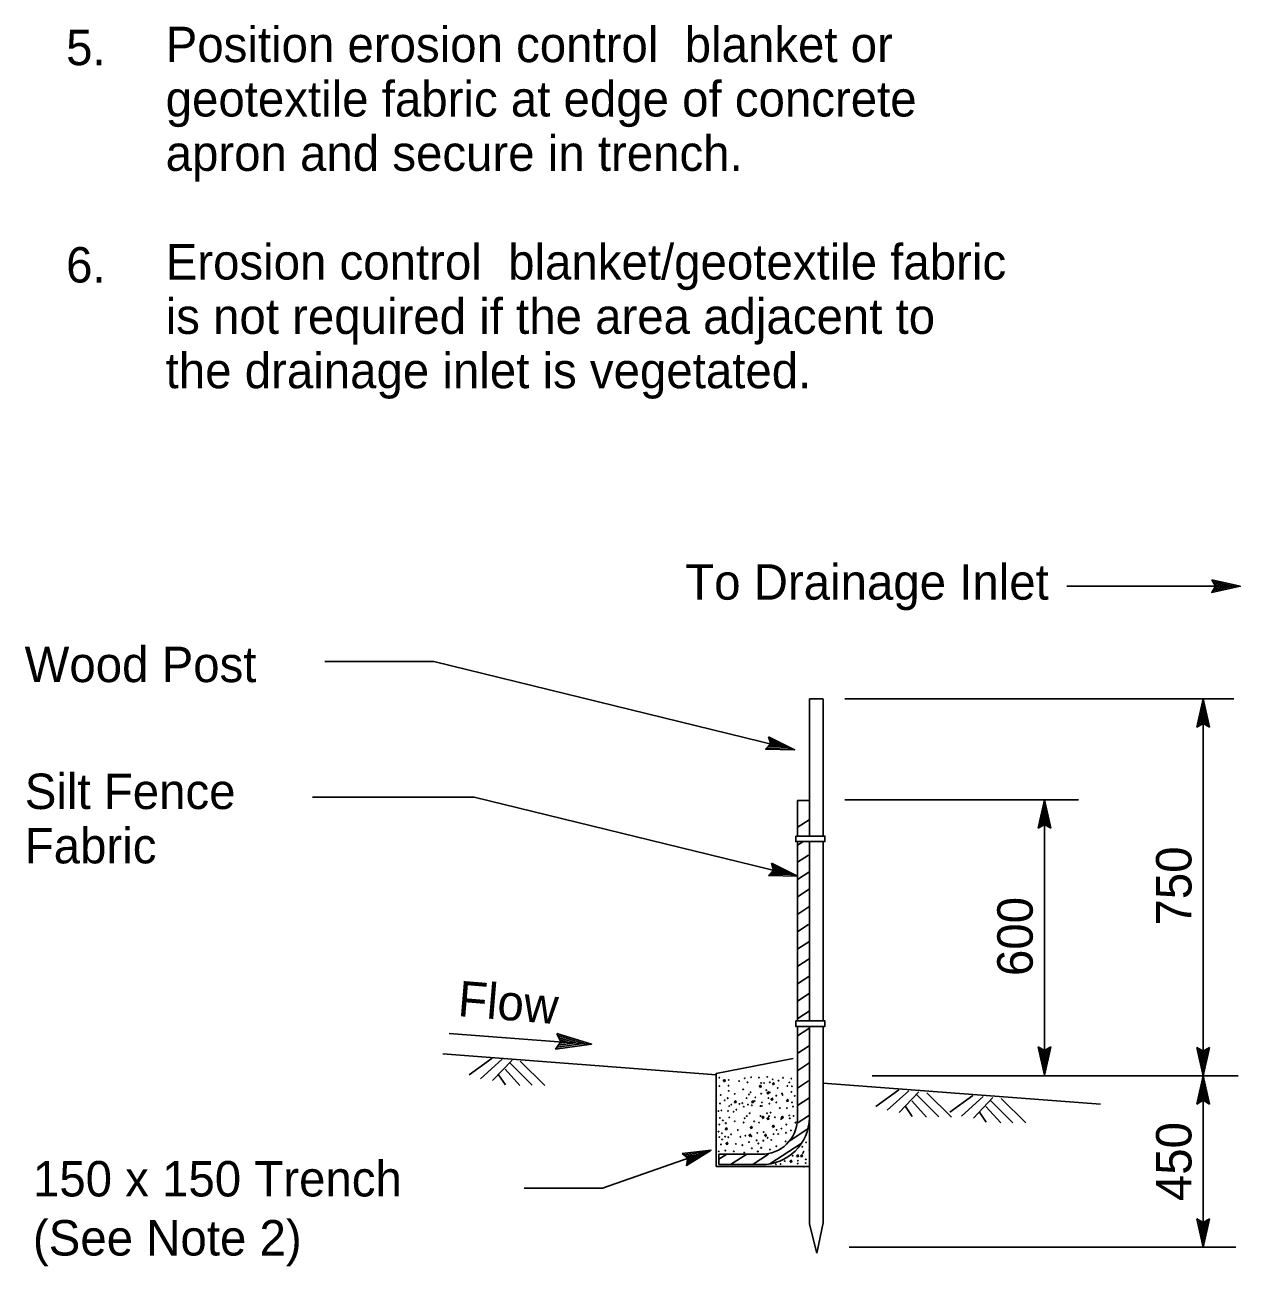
# Model space of a CAD drawing. Extents: x 6707406 to 6714471, y 1868570 to 1872341.
# Drawn here: x 6710120.7 to 6710367.6, y 1871743.9 to 1871996.1 of the extents above; entities that cross this region are included whole.
import ezdxf

# ---------------------------------------------------------------- set-up
doc = ezdxf.new("R2010")
doc.units = 0
for name, color, linetype in [('1 Control', 7, 'Continuous'), ('56 Stg 3 Anno', 7, 'Continuous'), ('57 Undefined', 7, 'Continuous'), ('59 Soundwall Ann', 7, 'Continuous'), ('60 Nongeo Data', 7, 'Continuous')]:
    doc.layers.add(name, color=color, linetype=linetype)

msp = doc.modelspace()

# ---------------------------------------------------------------- linework, layer by layer
at = {"layer": '1 Control'}
for p, q in [((6710361.8, 1871883.35), (6710361.8, 1871883.35)), ((6710361.8, 1871880.79), (6710361.8, 1871880.79)), ((6710367.56, 1871882.07), (6710367.56, 1871882.07)), ((6710271.77, 1871851.46), (6710271.77, 1871851.46)), ((6710271.16, 1871848.97), (6710271.16, 1871848.97)), ((6710277.06, 1871848.85), (6710277.06, 1871848.85)), ((6710228.77, 1871791.21), (6710228.77, 1871791.21)), ((6710235.82, 1871789.06), (6710235.82, 1871789.06)), ((6710228.52, 1871788.02), (6710228.52, 1871788.02))]:
    msp.add_line(p, q, dxfattribs=at)
for points in [[(6710361.8, 1871883.35), (6710367.56, 1871882.07), (6710361.8, 1871880.79), (6710362, 1871881.13), (6710366.22, 1871882.06), (6710362, 1871883.01), (6710362.21, 1871882.67), (6710364.91, 1871882.07), (6710362.21, 1871881.47), (6710362.41, 1871881.81), (6710363.58, 1871882.07), (6710362.41, 1871882.33), (6710362.57, 1871882.07), (6710361.8, 1871880.79), (6710362.57, 1871882.07)], [(6710271.77, 1871851.46), (6710277.06, 1871848.85), (6710271.16, 1871848.97), (6710271.44, 1871849.26), (6710275.76, 1871849.16), (6710271.89, 1871851.08), (6710272, 1871850.71), (6710274.48, 1871849.48), (6710271.72, 1871849.54), (6710272, 1871849.82), (6710273.2, 1871849.79), (6710272.12, 1871850.33), (6710272.21, 1871850.03), (6710271.16, 1871848.97), (6710272.21, 1871850.03)], [(6710228.77, 1871791.21), (6710235.82, 1871789.06), (6710228.52, 1871788.02), (6710228.81, 1871788.42), (6710234.16, 1871789.18), (6710228.99, 1871790.77), (6710229.21, 1871790.32), (6710232.52, 1871789.31), (6710229.1, 1871788.83), (6710229.39, 1871789.23), (6710230.87, 1871789.44), (6710229.43, 1871789.88), (6710229.6, 1871789.53), (6710228.52, 1871788.02), (6710229.6, 1871789.53)]]:
    msp.add_lwpolyline(points, close=True, dxfattribs=at)
at = {"layer": '56 Stg 3 Anno'}
for p, q in [((6710332.36, 1871882.07), (6710367.56, 1871882.07)), ((6710287.23, 1871859.19), (6710366.26, 1871859.19)), ((6710358.78, 1871853.43), (6710360.07, 1871859.19)), ((6710359.12, 1871853.63), (6710360.07, 1871857.86)), ((6710360.07, 1871782.62), (6710360.07, 1871859.19)), ((6710360.07, 1871859.19), (6710360.07, 1871859.19)), ((6710360.07, 1871859.19), (6710361.34, 1871853.43)), ((6710360.07, 1871857.85), (6710361, 1871853.65)), ((6710359.47, 1871853.86), (6710360.06, 1871856.53)), ((6710359.8, 1871854.03), (6710360.06, 1871855.21)), ((6710360.06, 1871856.53), (6710360.67, 1871853.82)), ((6710360.06, 1871855.21), (6710360.32, 1871854.05)), ((6710360.07, 1871854.19), (6710358.78, 1871853.43)), ((6710358.78, 1871853.43), (6710358.78, 1871853.43)), ((6710361.34, 1871853.43), (6710360.07, 1871854.19)), ((6710361.34, 1871853.43), (6710361.34, 1871853.43)), ((6710287.23, 1871838.66), (6710334.72, 1871838.66)), ((6710326.53, 1871832.9), (6710327.82, 1871838.66)), ((6710326.53, 1871832.9), (6710327.82, 1871838.66)), ((6710326.88, 1871833.11), (6710327.82, 1871837.33)), ((6710326.88, 1871833.11), (6710327.82, 1871837.33)), ((6710327.82, 1871782.74), (6710327.82, 1871838.66)), ((6710327.82, 1871838.66), (6710327.82, 1871838.66)), ((6710327.82, 1871838.66), (6710329.1, 1871832.9)), ((6710327.82, 1871838.66), (6710327.82, 1871838.66)), ((6710327.82, 1871838.66), (6710329.1, 1871832.9)), ((6710327.82, 1871837.32), (6710328.75, 1871833.12)), ((6710327.82, 1871837.32), (6710328.75, 1871833.12)), ((6710327.22, 1871833.33), (6710327.82, 1871836.01)), ((6710327.22, 1871833.33), (6710327.82, 1871836.01)), ((6710327.55, 1871833.5), (6710327.82, 1871834.68)), ((6710327.55, 1871833.5), (6710327.82, 1871834.68)), ((6710327.82, 1871836.01), (6710328.42, 1871833.3)), ((6710327.82, 1871836.01), (6710328.42, 1871833.3)), ((6710327.82, 1871834.68), (6710328.07, 1871833.52)), ((6710327.82, 1871834.68), (6710328.07, 1871833.52)), ((6710327.82, 1871833.67), (6710326.53, 1871832.9)), ((6710327.82, 1871833.67), (6710326.53, 1871832.9)), ((6710326.53, 1871832.9), (6710326.53, 1871832.9)), ((6710326.53, 1871832.9), (6710326.53, 1871832.9)), ((6710329.1, 1871832.9), (6710327.82, 1871833.67)), ((6710329.1, 1871832.9), (6710327.82, 1871833.67)), ((6710329.1, 1871832.9), (6710329.1, 1871832.9)), ((6710329.1, 1871832.9), (6710329.1, 1871832.9)), ((6710271.74, 1871823.29), (6710272.79, 1871824.35)), ((6710272.79, 1871824.35), (6710272.35, 1871825.78)), ((6710272.35, 1871825.78), (6710272.35, 1871825.78)), ((6710272.35, 1871825.78), (6710277.64, 1871823.16)), ((6710272.47, 1871825.4), (6710276.35, 1871823.48)), ((6710272.61, 1871825.01), (6710275.06, 1871823.79)), ((6710272.69, 1871824.65), (6710273.78, 1871824.11)), ((6710277.64, 1871823.16), (6710271.74, 1871823.29)), ((6710271.74, 1871823.29), (6710271.74, 1871823.29)), ((6710276.34, 1871823.48), (6710272.04, 1871823.57)), ((6710275.06, 1871823.79), (6710272.29, 1871823.85)), ((6710273.78, 1871824.11), (6710272.59, 1871824.14)), ((6710277.64, 1871823.16), (6710277.64, 1871823.16)), ((6710327.82, 1871782.74), (6710326.54, 1871788.5)), ((6710326.54, 1871788.5), (6710326.54, 1871788.5)), ((6710326.54, 1871788.5), (6710327.82, 1871787.73)), ((6710327.82, 1871784.07), (6710326.89, 1871788.27)), ((6710327.82, 1871785.39), (6710327.22, 1871788.1)), ((6710327.82, 1871786.71), (6710327.57, 1871787.88)), ((6710327.82, 1871787.73), (6710329.11, 1871788.5)), ((6710329.11, 1871788.5), (6710327.82, 1871782.74)), ((6710328.77, 1871788.29), (6710327.82, 1871784.06)), ((6710328.42, 1871788.06), (6710327.82, 1871785.39)), ((6710328.09, 1871787.89), (6710327.82, 1871786.71)), ((6710329.11, 1871788.5), (6710329.11, 1871788.5)), ((6710360.07, 1871782.62), (6710358.79, 1871788.38)), ((6710358.79, 1871788.38), (6710358.79, 1871788.38)), ((6710358.79, 1871788.38), (6710360.07, 1871787.61)), ((6710360.06, 1871783.95), (6710359.13, 1871788.15)), ((6710360.07, 1871785.27), (6710359.47, 1871787.98)), ((6710360.07, 1871786.6), (6710359.81, 1871787.76)), ((6710360.07, 1871787.61), (6710361.35, 1871788.38)), ((6710361.35, 1871788.38), (6710360.07, 1871782.62)), ((6710361.01, 1871788.17), (6710360.07, 1871783.94)), ((6710360.67, 1871787.95), (6710360.07, 1871785.27)), ((6710360.33, 1871787.78), (6710360.07, 1871786.6)), ((6710361.35, 1871788.38), (6710361.35, 1871788.38)), ((6710292.82, 1871782.62), (6710367.14, 1871782.62)), ((6710327.82, 1871782.74), (6710327.82, 1871782.74)), ((6710358.78, 1871776.86), (6710360.07, 1871782.62)), ((6710360.07, 1871747.79), (6710360.07, 1871782.62)), ((6710360.07, 1871782.62), (6710360.07, 1871782.62)), ((6710360.07, 1871782.62), (6710360.07, 1871782.62)), ((6710360.07, 1871782.62), (6710361.34, 1871776.86)), ((6710359.12, 1871777.07), (6710360.07, 1871781.29)), ((6710359.47, 1871777.29), (6710360.06, 1871779.97)), ((6710360.06, 1871779.97), (6710360.67, 1871777.25)), ((6710360.07, 1871781.28), (6710361, 1871777.08)), ((6710360.07, 1871777.63), (6710358.78, 1871776.86)), ((6710358.78, 1871776.86), (6710358.78, 1871776.86)), ((6710359.8, 1871777.46), (6710360.06, 1871778.64)), ((6710360.06, 1871778.64), (6710360.32, 1871777.48)), ((6710361.34, 1871776.86), (6710360.07, 1871777.63)), ((6710361.34, 1871776.86), (6710361.34, 1871776.86)), ((6710260.09, 1871767.51), (6710238.07, 1871759.75)), ((6710360.07, 1871747.79), (6710358.79, 1871753.55)), ((6710358.79, 1871753.55), (6710358.79, 1871753.55)), ((6710358.79, 1871753.55), (6710360.07, 1871752.78)), ((6710360.06, 1871749.13), (6710359.13, 1871753.33)), ((6710360.07, 1871750.44), (6710359.47, 1871753.16)), ((6710360.07, 1871751.77), (6710359.81, 1871752.93)), ((6710360.07, 1871752.78), (6710361.35, 1871753.55)), ((6710361.35, 1871753.55), (6710360.07, 1871747.79)), ((6710361.01, 1871753.34), (6710360.07, 1871749.12)), ((6710360.67, 1871753.12), (6710360.07, 1871750.44)), ((6710360.33, 1871752.95), (6710360.07, 1871751.77)), ((6710361.35, 1871753.55), (6710361.35, 1871753.55)), ((6710288.11, 1871747.79), (6710366.7, 1871747.79)), ((6710360.07, 1871747.79), (6710360.07, 1871747.79))]:
    msp.add_line(p, q, dxfattribs=at)
for points in [[(6710203.78, 1871866.76), (6710181.62, 1871866.76)], [(6710203.78, 1871866.76), (6710277.06, 1871848.85)], [(6710179.15, 1871839.22), (6710211.96, 1871839.22)], [(6710211.96, 1871839.22), (6710277.64, 1871823.16)], [(6710222.12, 1871759.75), (6710238.07, 1871759.75)]]:
    msp.add_lwpolyline(points, dxfattribs=at)
at = {"layer": '57 Undefined'}
msp.add_line((6710268.64, 1871764.64), (6710271.77, 1871766.67), dxfattribs=at)
at = {"layer": '59 Soundwall Ann'}
for p, q in [((6710277.59, 1871833.05), (6710280.03, 1871834.63)), ((6710277.63, 1871829.43), (6710278.75, 1871830.16)), ((6710277.64, 1871826.02), (6710279.86, 1871827.46)), ((6710277.64, 1871822.49), (6710279.93, 1871823.97)), ((6710277.64, 1871818.96), (6710280.02, 1871820.5)), ((6710277.68, 1871815.45), (6710279.97, 1871816.93)), ((6710277.68, 1871811.92), (6710279.91, 1871813.36)), ((6710277.71, 1871808.4), (6710279.95, 1871809.85)), ((6710277.73, 1871804.88), (6710280, 1871806.35)), ((6710277.67, 1871801.31), (6710279.95, 1871802.79)), ((6710277.66, 1871797.77), (6710280, 1871799.29)), ((6710277.69, 1871794.26), (6710279.99, 1871795.75)), ((6710277.67, 1871790.71), (6710279.98, 1871792.21)), ((6710277.71, 1871787.21), (6710280.01, 1871788.7)), ((6710215.6, 1871786.2), (6710210.93, 1871782.8)), ((6710217.66, 1871785.98), (6710213.25, 1871782.02)), ((6710219.67, 1871785.78), (6710215.69, 1871781.62)), ((6710218.25, 1871783.98), (6710221.27, 1871780.64)), ((6710219.25, 1871785.14), (6710223.72, 1871780.67)), ((6710221.32, 1871785.6), (6710226.32, 1871780.61)), ((6710277.72, 1871783.68), (6710279.96, 1871785.14)), ((6710216.94, 1871782.8), (6710218.31, 1871780.75)), ((6710277.65, 1871780.11), (6710279.9, 1871781.56)), ((6710298.21, 1871779.77), (6710293.54, 1871776.36)), ((6710300.27, 1871779.54), (6710295.86, 1871775.59)), ((6710302.28, 1871779.35), (6710298.3, 1871775.18)), ((6710303.93, 1871779.17), (6710308.93, 1871774.18)), ((6710277.64, 1871776.57), (6710279.97, 1871778.07)), ((6710299.55, 1871776.37), (6710300.92, 1871774.31)), ((6710300.86, 1871777.55), (6710303.88, 1871774.21)), ((6710301.86, 1871778.71), (6710306.33, 1871774.24)), ((6710313.28, 1871778.61), (6710308.61, 1871775.2)), ((6710315.34, 1871778.38), (6710310.93, 1871774.43)), ((6710317.35, 1871778.19), (6710313.37, 1871774.02)), ((6710315.93, 1871776.39), (6710318.95, 1871773.05)), ((6710316.94, 1871777.55), (6710321.4, 1871773.08)), ((6710319, 1871778.01), (6710324, 1871773.02)), ((6710280.06, 1871774.6), (6710277.56, 1871772.98)), ((6710314.63, 1871775.21), (6710316, 1871773.15)), ((6710276.13, 1871769.49), (6710279.76, 1871771.84)), ((6710272.03, 1871764.71), (6710278.41, 1871768.84)), ((6710261.69, 1871765.64), (6710263.32, 1871766.7)), ((6710264.04, 1871764.57), (6710267.33, 1871766.7))]:
    msp.add_line(p, q, dxfattribs=at)
for points in [[(6710262.55, 1871781.5), (6710262.82, 1871781.83), (6710262.93, 1871781.5), (6710262.6, 1871781.39)], [(6710269.88, 1871780.34), (6710270.15, 1871780.67), (6710270.26, 1871780.34), (6710269.93, 1871780.23)], [(6710271.45, 1871779.04), (6710271.72, 1871779.37), (6710271.83, 1871779.04), (6710271.5, 1871778.93)], [(6710272.5, 1871780.87), (6710272.77, 1871781.2), (6710272.88, 1871780.87), (6710272.55, 1871780.76)], [(6710264.77, 1871777.19), (6710265.05, 1871777.52), (6710265.16, 1871777.19), (6710264.83, 1871777.08)], [(6710268.31, 1871777.21), (6710268.58, 1871777.54), (6710268.69, 1871777.21), (6710268.36, 1871777.1)], [(6710272.23, 1871777.73), (6710272.51, 1871778.06), (6710272.62, 1871777.73), (6710272.29, 1871777.62)], [(6710275.38, 1871777.47), (6710275.65, 1871777.8), (6710275.76, 1871777.47), (6710275.43, 1871777.36)], [(6710270.4, 1871774.07), (6710270.67, 1871774.4), (6710270.78, 1871774.07), (6710270.46, 1871773.96)], [(6710271.45, 1871773.81), (6710271.72, 1871774.14), (6710271.83, 1871773.81), (6710271.5, 1871773.7)], [(6710274.33, 1871774.07), (6710274.6, 1871774.4), (6710274.71, 1871774.07), (6710274.38, 1871773.96)], [(6710262.96, 1871771.71), (6710263.24, 1871772.04), (6710263.35, 1871771.71), (6710263.02, 1871771.6)], [(6710268.04, 1871771.98), (6710268.32, 1871772.31), (6710268.43, 1871771.98), (6710268.1, 1871771.87)], [(6710272.5, 1871772.24), (6710272.77, 1871772.57), (6710272.88, 1871772.24), (6710272.55, 1871772.13)], [(6710263.1, 1871768.74), (6710263.38, 1871769.07), (6710263.49, 1871768.74), (6710263.16, 1871768.63)], [(6710267.78, 1871770.41), (6710268.06, 1871770.74), (6710268.17, 1871770.41), (6710267.84, 1871770.3)], [(6710270.92, 1871770.41), (6710271.2, 1871770.74), (6710271.31, 1871770.41), (6710270.98, 1871770.3)], [(6710277.47, 1871766.23), (6710277.74, 1871766.56), (6710277.85, 1871766.23), (6710277.52, 1871766.12)], [(6710278.26, 1871766.23), (6710278.53, 1871766.56), (6710278.64, 1871766.23), (6710278.31, 1871766.12)], [(6710276.09, 1871765.13), (6710276.37, 1871765.46), (6710276.48, 1871765.13), (6710276.15, 1871765.02)]]:
    msp.add_lwpolyline(points, dxfattribs=at)
for centre in [(6710261.79, 1871782.22), (6710263.69, 1871781.76), (6710265.78, 1871781.53), (6710266.92, 1871782.1), (6710267.49, 1871781.3), (6710268.22, 1871782.32), (6710269.8, 1871782.24), (6710271.51, 1871782.38), (6710272.03, 1871781.3), (6710272.62, 1871781.88), (6710273.79, 1871781.59), (6710274.72, 1871782.19), (6710276.42, 1871782.03), (6710261.79, 1871780.51), (6710263.64, 1871780.6), (6710263.69, 1871779.53), (6710264.89, 1871778.93), (6710266.61, 1871779.83), (6710267.79, 1871778.81), (6710268.12, 1871779.26), (6710270.27, 1871781.15), (6710270.27, 1871778.95), (6710270.86, 1871781.15), (6710271.3, 1871779.68), (6710272.03, 1871779.25), (6710273.64, 1871780.12), (6710274.5, 1871779), (6710275.6, 1871780.53), (6710275.98, 1871781.25), (6710276.42, 1871779.33), (6710276.51, 1871780.47), (6710261.93, 1871776.98), (6710262.06, 1871778.7), (6710262.88, 1871777.62), (6710263.46, 1871778.06), (6710263.79, 1871776.46), (6710264.23, 1871776.75), (6710265.84, 1871776.9), (6710266.42, 1871777.04), (6710266.72, 1871776.31), (6710267.3, 1871778.07), (6710267.59, 1871776.75), (6710268.37, 1871776.61), (6710268.96, 1871777.49), (6710269.1, 1871778.22), (6710270.13, 1871776.46), (6710270.42, 1871777.2), (6710270.42, 1871776.46), (6710271.74, 1871778.07), (6710271.93, 1871776.94), (6710273.35, 1871778.57), (6710273.35, 1871777.2), (6710274.61, 1871778.73), (6710276.53, 1871777.2), (6710276.73, 1871776.35), (6710277.08, 1871778.52), (6710261.59, 1871775.43), (6710261.88, 1871774.05), (6710262.18, 1871775.58), (6710263.55, 1871775.45), (6710263.78, 1871774.15), (6710264.67, 1871775.29), (6710265.25, 1871775.72), (6710266.91, 1871773.97), (6710267.35, 1871774.41), (6710267.93, 1871775), (6710270.13, 1871774.41), (6710271.45, 1871775), (6710271.88, 1871774.41), (6710272.18, 1871775.14), (6710273.07, 1871774.18), (6710274.06, 1871776.04), (6710274.33, 1871773.8), (6710275.49, 1871776.04), (6710275.49, 1871776.04), (6710275.98, 1871774.56), (6710276.09, 1871773.96), (6710276.85, 1871774.46), (6710261.6, 1871771.27), (6710261.74, 1871772.71), (6710262.48, 1871773.54), (6710263.09, 1871772.98), (6710264.89, 1871773.36), (6710265.54, 1871771.59), (6710266.7, 1871773.12), (6710268.84, 1871773.36), (6710269.84, 1871773.09), (6710273.4, 1871771.61), (6710274.39, 1871771.88), (6710275.38, 1871772.7), (6710276.31, 1871771.5), (6710277.24, 1871773.08), (6710261.74, 1871770.15), (6710262.3, 1871770.94), (6710262.34, 1871769.69), (6710262.34, 1871769.69), (6710262.95, 1871770.25), (6710263.6, 1871770.11), (6710264.15, 1871770.71), (6710265.13, 1871768.76), (6710266.05, 1871770.2), (6710267.06, 1871770.44), (6710267.79, 1871769.14), (6710268.28, 1871770.32), (6710269.35, 1871769.49), (6710269.46, 1871771.01), (6710269.69, 1871768.85), (6710270.71, 1871769.43), (6710270.77, 1871771.16), (6710271.58, 1871770), (6710272.32, 1871769.58), (6710272.78, 1871770.76), (6710273.73, 1871770.78), (6710275.24, 1871769.27), (6710275.3, 1871771.02), (6710279.38, 1871769.08), (6710261.65, 1871767.23), (6710262.11, 1871768.67), (6710262.99, 1871767.41), (6710264.71, 1871767.27), (6710266.44, 1871768.51), (6710266.83, 1871767.01), (6710268.37, 1871767.89), (6710269.59, 1871767.22), (6710270.27, 1871767.97), (6710272.05, 1871767.61), (6710273.35, 1871768.29), (6710276.66, 1871766.36), (6710278.63, 1871768.2), (6710278.74, 1871766.91), (6710278.88, 1871767.17), (6710280.03, 1871767.51), (6710273.25, 1871764.63), (6710274.22, 1871764.67), (6710275.06, 1871765.28), (6710277.7, 1871764.77), (6710277.72, 1871765.35), (6710278.93, 1871764.17), (6710279.32, 1871764.86), (6710279.34, 1871765.62)]:
    msp.add_ellipse(centre, major_axis=(0.0548, 0), ratio=0.999983, dxfattribs=at)
at = {"layer": '60 Nongeo Data'}
for p, q in [((6710280.06, 1871859.19), (6710282.76, 1871859.19)), ((6710277.64, 1871831.33), (6710277.64, 1871838.53)), ((6710277.64, 1871793.74), (6710277.64, 1871830.21)), ((6710277.64, 1871773.78), (6710277.64, 1871792.63)), ((6710235.33, 1871789.06), (6710206.89, 1871791.23)), ((6710261.14, 1871782.8), (6710205.58, 1871787.05)), ((6710339.18, 1871776.83), (6710282.88, 1871781.14)), ((6710254.23, 1871766.81), (6710254.23, 1871766.81)), ((6710260.09, 1871767.51), (6710260.09, 1871767.51)), ((6710261.69, 1871764.57), (6710261.69, 1871766.7)), ((6710261.69, 1871766.7), (6710270.27, 1871766.7)), ((6710255.08, 1871764.4), (6710255.08, 1871764.4)), ((6710261.69, 1871764.57), (6710270.27, 1871764.57)), ((6710280.06, 1871752.45), (6710281.56, 1871746.59)), ((6710281.56, 1871746.57), (6710282.88, 1871752.72))]:
    msp.add_line(p, q, dxfattribs=at)
for points in [[(6710280.06, 1871859.19), (6710280.06, 1871831.32)], [(6710282.88, 1871831.31), (6710282.88, 1871859.19)], [(6710280.05, 1871838.53), (6710277.64, 1871838.53), (6710277.64, 1871838.11)], [(6710280.06, 1871830.17), (6710280.06, 1871793.74)], [(6710282.88, 1871793.74), (6710282.88, 1871830.2)], [(6710280.06, 1871792.63), (6710280.06, 1871752.45)], [(6710282.88, 1871752.72), (6710282.88, 1871792.63)], [(6710276.75, 1871786.1), (6710261.14, 1871783.09), (6710261.14, 1871764.18), (6710280.06, 1871764.18), (6710280.06, 1871781.9)]]:
    msp.add_lwpolyline(points, dxfattribs=at)
for points in [[(6710277.28, 1871831.29), (6710283.21, 1871831.29), (6710283.21, 1871830.18), (6710277.28, 1871830.18)], [(6710277.29, 1871793.74), (6710283.22, 1871793.74), (6710283.22, 1871792.63), (6710277.29, 1871792.63)], [(6710254.23, 1871766.81), (6710260.09, 1871767.51), (6710255.08, 1871764.4), (6710255.16, 1871764.78), (6710258.83, 1871767.07), (6710254.54, 1871766.56), (6710254.84, 1871766.31), (6710257.59, 1871766.63), (6710255.24, 1871765.17), (6710255.32, 1871765.56), (6710256.34, 1871766.2), (6710255.15, 1871766.05), (6710255.38, 1871765.86), (6710255.08, 1871764.4), (6710255.38, 1871765.86)]]:
    msp.add_lwpolyline(points, close=True, dxfattribs=at)
for centre, major_axis in [((6710270.39, 1871774.25), (-9.68, 0)), ((6710270.39, 1871773.9), (-7.23, 0))]:
    msp.add_ellipse(centre, major_axis=major_axis, ratio=0.999983, start_param=1.559282, end_param=3.125268, dxfattribs=at)
msp.add_ellipse((6710272.45, 1871764.94), major_axis=(0.0548, 0), ratio=0.999983, dxfattribs=at)

# ---------------------------------------------------------------- texts
at = {"layer": '57 Undefined'}
for s, height, p in [('Position erosion control  blanket or ', 7.1998, (6710149.31, 1871988.53)), ('5.', 7.2, (6710129.09, 1871987.92)), ('geotextile fabric at edge of concrete ', 7.1998, (6710149.31, 1871977.49)), ('apron and secure in trench.', 7.1998, (6710149.31, 1871966.45)), ('6.', 7.2, (6710129.09, 1871943.76)), ('Erosion control  blanket/geotextile fabric ', 7.1998, (6710149.31, 1871944.37)), ('is not required if the area adjacent to ', 7.1998, (6710149.31, 1871933.33)), ('the drainage inlet is vegetated.', 7.1998, (6710149.31, 1871922.29)), ('To Drainage Inlet', 7.1998, (6710254.84, 1871879.33)), ('Wood Post', 7.2, (6710120.66, 1871862.58)), ('Silt Fence', 7.2, (6710120.69, 1871836.8)), ('Fabric', 7.2, (6710120.69, 1871825.76)), ('150 x 150 Trench ', 7.1998, (6710122.35, 1871758.09)), ('(See Note 2)', 7.1998, (6710122.35, 1871746.09))]:
    msp.add_text(s, height=height, dxfattribs=at).set_placement(p)
for s, rotation, p in [('750', 90, (6710357.67, 1871813.13)), ('600', 90, (6710325.42, 1871802.87)), ('Flow', 355.2879, (6710208.49, 1871794.75)), ('450', 90, (6710357.67, 1871757.14))]:
    msp.add_text(s, height=7.2, rotation=rotation, dxfattribs=at).set_placement(p)

doc.saveas('drawing.dxf')
